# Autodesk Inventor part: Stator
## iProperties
Author: Philippe
Shininess: 29.0
Angle Display Precision: 2
Document Length Units: 11269
Document Angle Units: 11283
Document Time Units: 11279
Document Mass Units: 11290
Document Length Units Precision: 3
Document Angle Units Precision: 2
Compacted: False
PropertySet Name: _Private Model Information
Created: 2002-08
Part Number: Stator
Material: Acier doux
Document SubType Name: Modélisation
Designer: Philippe
Control State: 0
Master: False
Checked Out: False
PropertySet Name: Design Tracking Control
Density: 7.859999999999999
Volumn: 49.02363375267539
Area: 240.1478825311544
PropertySet Name: Model Information
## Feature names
1. Révolution1 [Revolution]
2. Extrusion1
3. Réseau circulaire1 [Circular Pattern]
4. Congé2 [Fillet]
5. Extrusion2
6. Réseau circulaire2 [Circular Pattern]
7. Extrusion3
8. Extrusion4
9. Extrusion5
10. Réseau circulaire3 [Circular Pattern]
